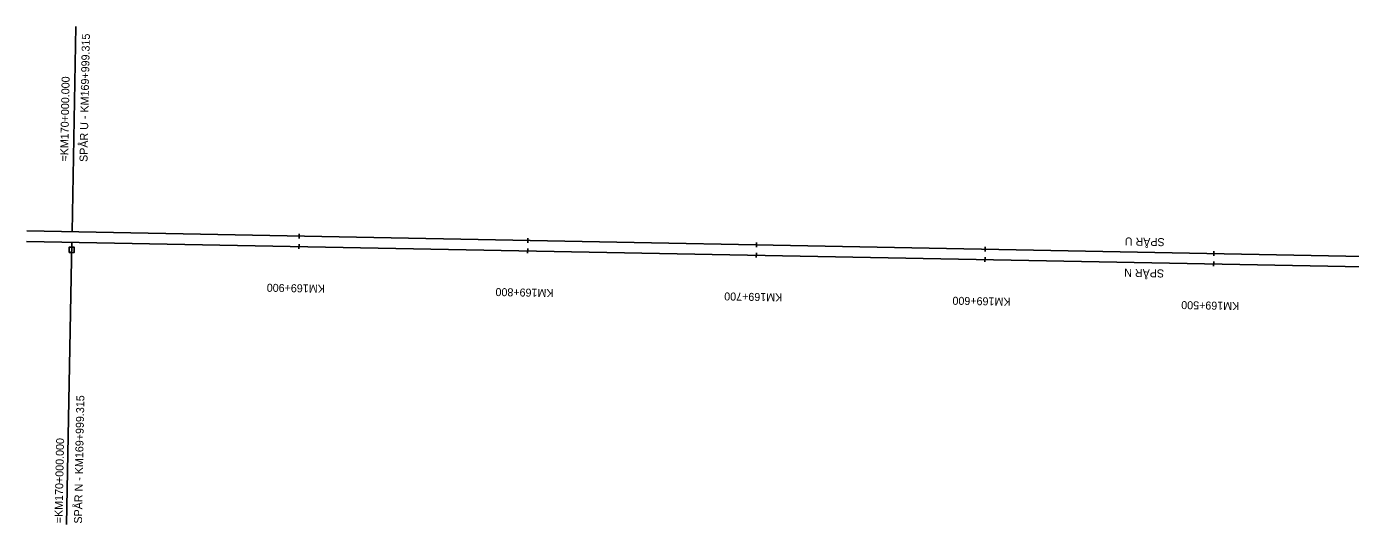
# Model space of a CAD drawing. Extents: x 185262 to 188870, y 6548921 to 6550022.
# Drawn here: x 185262 to 185841, y 6549805 to 6550022 of the extents above; entities that cross this region are included whole.
import ezdxf

# ---------------------------------------------------------------- set-up
doc = ezdxf.new("R2010")
doc.units = 0
for name, color, linetype in [('Kilometertavla P', 7, 'Continuous'), ('Konnektion längdmätning L', 7, 'Continuous'), ('Konnektion längdmätning T', 7, 'Continuous'), ('Längdm markering (primär) L', 7, 'Continuous'), ('Längdmätning T', 7, 'Continuous'), ('Spår bef projekterat behålls L', 7, 'Continuous'), ('Spår nr T', 7, 'Continuous')]:
    doc.layers.add(name, color=color, linetype=linetype)

msp = doc.modelspace()

# ---------------------------------------------------------------- linework, layer by layer
at = {"layer": 'Kilometertavla P'}
msp.add_lwpolyline([(185281.06, 6549923.82), (185283.31, 6549923.82), (185283.31, 6549926.07), (185281.06, 6549926.07)], close=True, dxfattribs=at)
at = {"layer": 'Konnektion längdmätning L'}
for points in [[(185282.33, 6549932.78), (185284.03, 6550022.49)], [(185282.25, 6549928.26), (185279.91, 6549804.93)]]:
    msp.add_lwpolyline(points, dxfattribs=at)
at = {"layer": 'Längdm markering (primär) L'}
for points in [[(185381.61, 6549929.9), (185381.65, 6549931.9)], [(185481.59, 6549928), (185481.63, 6549930)], [(185381.52, 6549925.37), (185381.56, 6549927.37)], [(185481.51, 6549923.48), (185481.54, 6549925.48)], [(185581.49, 6549921.58), (185581.53, 6549923.58)], [(185581.57, 6549926.1), (185581.61, 6549928.1)], [(185681.56, 6549924.21), (185681.59, 6549926.21)], [(185781.54, 6549922.31), (185781.58, 6549924.31)], [(185681.47, 6549919.68), (185681.51, 6549921.68)], [(185781.45, 6549917.79), (185781.49, 6549919.79)]]:
    msp.add_lwpolyline(points, dxfattribs=at)
at = {"layer": 'Spår bef projekterat behålls L'}
for p, q in [((186401.75, 6549911.55), (185262.5, 6549933.16)), ((186440.01, 6549906.29), (185262.41, 6549928.63))]:
    msp.add_line(p, q, dxfattribs=at)

# ---------------------------------------------------------------- texts
at = {"layer": 'Konnektion längdmätning T'}
for s, p in [('SPÅR U - KM169+999.315', (185289.09, 6549963.29)), ('=KM170+000.000 ', (185280.59, 6549963.45)), ('SPÅR N - KM169+999.315', (185286.67, 6549805.3)), ('=KM170+000.000', (185278.17, 6549805.46))]:
    msp.add_text(s, height=3.5, rotation=88.91329, dxfattribs=at).set_placement(p)
at = {"layer": 'Längdmätning T'}
for s, p in [('KM169+900', (185392.87, 6549909.65)), ('KM169+800', (185492.87, 6549907.76)), ('KM169+700', (185592.89, 6549905.86)), ('KM169+600', (185692.67, 6549903.97)), ('KM169+500', (185792.69, 6549902.07))]:
    msp.add_text(s, height=3.5, rotation=178.91329, dxfattribs=at).set_placement(p)
at = {"layer": 'Spår nr T'}
for s, p in [('SPÅR U', (185760.06, 6549930.02)), ('SPÅR N', (185759.8, 6549916.33))]:
    msp.add_text(s, height=3.5, rotation=178.91329, dxfattribs=at).set_placement(p)

doc.saveas('drawing.dxf')
